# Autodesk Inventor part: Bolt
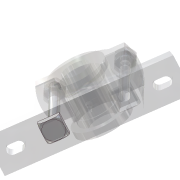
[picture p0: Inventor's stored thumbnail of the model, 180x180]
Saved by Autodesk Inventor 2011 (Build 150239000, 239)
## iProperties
Shininess: 77.0
Length Units: 11269
Angle Units: 11279
Time Units: 11290
Mass Units: 11283
Length Display Precision: 3
Angle Display Precision: 2
Created: 2002-02
Part Number: Bolt
Document SubType Name: Modeling
Designer: ***
Density: 1 g/cm^3
Density: 0.0
Volumn: 0.0
Area: 0.0
PropertySet Name: Model Information
Control State: 0
Master: False
Checked Out: False
Author: ***
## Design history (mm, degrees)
sketch "Sketch1"
  geometry: C1 r 16.971 at (0, 0); 3 further points
  constraints: 2 coincident, 1 centre point, 2 other
extrude "Extrusion1" new body sketch "Sketch1" distance "d1" = 8; taper "d2" = 0 deg
fillet "Fillet1" dims "d3" = 5
sketch "Sketch2"
  geometry: L1 (12, -12)-(-12, -12); L2 (-12, -12)-(-12, 12); L3 (-12, 12)-(12, 12); L4 (12, 12)-(12, -12); C1 r 9 at (0, 0) reference; 2 further points
  constraints: 8 end point, 1 coincident, 1 midpoint, 7 other
extrude "Extrusion2" sketch "Sketch2" stored distance "d4" = 8; taper "d5" = 0 deg
sketch "Sketch3"
  geometry: C1 r 6 at (0, 0)
  constraints: 1 centre point
extrude "Extrusion3" join sketch "Sketch3" distance "d7" = 96; taper "d8" = 0 deg
body "Solid1"
